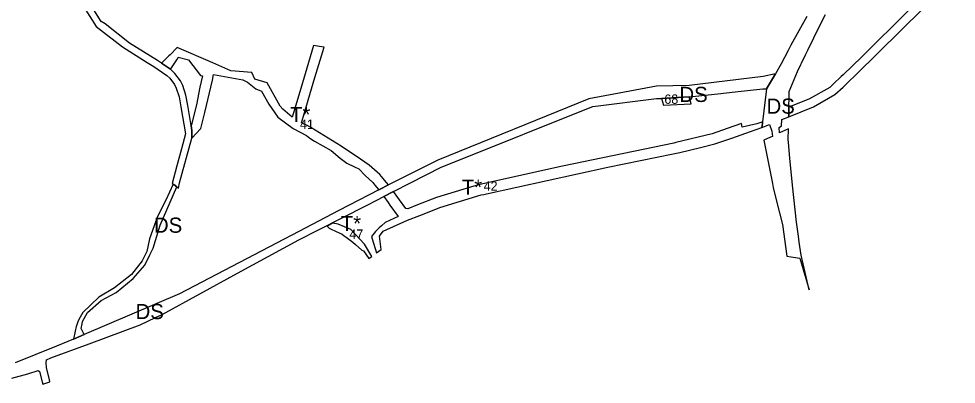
# Model space of a CAD drawing. Extents: x -535435 to -532834, y -1165802 to -1163866.
# Drawn here: x -534910 to -534109, y -1165571 to -1165258 of the extents above; entities that cross this region are included whole.
import ezdxf

# ---------------------------------------------------------------- set-up
doc = ezdxf.new("R2010")
doc.units = 0
for name, color, linetype in [('Level 23', 7, 'Continuous'), ('Level 4', 7, 'Continuous'), ('Level 44', 7, 'Continuous'), ('Level 5', 7, 'Continuous'), ('Level 61', 7, 'Continuous')]:
    doc.layers.add(name, color=color, linetype=linetype)

msp = doc.modelspace()

# ---------------------------------------------------------------- linework, layer by layer
at = {"layer": 'Level 23'}
msp.add_lwpolyline([(-534101.59, -1165203.84), (-534114.18, -1165216.32), (-534139.47, -1165241.41), (-534149.08, -1165250.94), (-534189.23, -1165290.59), (-534205.1, -1165305.99), (-534206.83, -1165307.61), (-534213.44, -1165313.82), (-534213.98, -1165314.34), (-534216.74, -1165316.93), (-534233.95, -1165326.61), (-534251.58, -1165333.78), (-534251.69, -1165338.72), (-534251.77, -1165341.96), (-534230.69, -1165333.38), (-534212.27, -1165323.02), (-534205.31, -1165316.61), (-534200.89, -1165312.54), (-534194.29, -1165306.12), (-534136.8, -1165249.37), (-534066.72, -1165179.82)], dxfattribs=at)
for points in [[(-534619.01, -1165386.65), (-534613.51, -1165392.33), (-534607, -1165398.33), (-534605.19, -1165400.54), (-534601.98, -1165404.46), (-534601.41, -1165404.16), (-534593.74, -1165400.31), (-534597.03, -1165396.3), (-534598.22, -1165394.85), (-534601.04, -1165391.41), (-534610.25, -1165383.45), (-534617.67, -1165378.23), (-534633.99, -1165367.14), (-534659.9, -1165351.07), (-534662.08, -1165350.11), (-534668.1, -1165347.2), (-534666.39, -1165341.5), (-534660.84, -1165323.06), (-534656.47, -1165308.49), (-534648.66, -1165282.51), (-534652.53, -1165281.94), (-534657.63, -1165281.08), (-534664.91, -1165305.3), (-534669.52, -1165320.65), (-534674.9, -1165338.55), (-534676.02, -1165342.29), (-534683.83, -1165335.46), (-534686.22, -1165332.95), (-534697.27, -1165312.9), (-534707.83, -1165309.96), (-534710.5, -1165304.17), (-534728.29, -1165302.64), (-534743.59, -1165295.91), (-534774.18, -1165282.74), (-534780.22, -1165288.91), (-534781.18, -1165289.9), (-534787.43, -1165296.27), (-534779.82, -1165301.36), (-534779.49, -1165300.88), (-534774.33, -1165293.32), (-534773.48, -1165292.09), (-534773.21, -1165290.92), (-534764.53, -1165293.41), (-534754.18, -1165306.73), (-534752.46, -1165306.87), (-534754.69, -1165316.58), (-534757.69, -1165331.84), (-534762.29, -1165349.74), (-534761.63, -1165353.69), (-534761.79, -1165360.41), (-534753.85, -1165351.98), (-534750.68, -1165338.49), (-534744.13, -1165310.57), (-534743.05, -1165305.98), (-534718.12, -1165310.44), (-534714.04, -1165312.46), (-534706.87, -1165318.09), (-534702.17, -1165320.06), (-534695.88, -1165331.28), (-534688.17, -1165342.38), (-534675.04, -1165351.98), (-534663.67, -1165357.97), (-534660.93, -1165360.38), (-534656.81, -1165362.85), (-534642.55, -1165370.75), (-534634.89, -1165377.36), (-534629.25, -1165381.75), (-534622.61, -1165384.94)], [(-534567.01, -1165426.39), (-534554.75, -1165421.51), (-534549.73, -1165419.5), (-534514.4, -1165408.9), (-534512.18, -1165408.41), (-534509.97, -1165407.93), (-534406.37, -1165385.09), (-534350.42, -1165373.76), (-534347.57, -1165373.21), (-534344.67, -1165372.49), (-534327.1, -1165368.26), (-534314.72, -1165365.27), (-534300.23, -1165360.21), (-534284.53, -1165354.73), (-534274.64, -1165351.27), (-534274.2, -1165347.69), (-534274.04, -1165346.4), (-534275.59, -1165346.89), (-534279.12, -1165348.18), (-534291.43, -1165350.78), (-534292.02, -1165347.81), (-534304.23, -1165352.07), (-534317.27, -1165356.63), (-534348.18, -1165364.09), (-534349.96, -1165364.5), (-534444.99, -1165384.39), (-534513.15, -1165399.41), (-534517.58, -1165400.46), (-534520.7, -1165401.39), (-534552.7, -1165411), (-534568.84, -1165417.43), (-534577.13, -1165420.74), (-534578.84, -1165420.53), (-534584.33, -1165412.96), (-534585.71, -1165411.05), (-534589.33, -1165406.05), (-534597.58, -1165410.25), (-534593.89, -1165415.47), (-534592.44, -1165417.51), (-534585.47, -1165427.37), (-534596.58, -1165432.42), (-534599.52, -1165435.21), (-534601.57, -1165437.17), (-534604.65, -1165440.1), (-534608.12, -1165444.51), (-534607.55, -1165446.4), (-534603.88, -1165458.54), (-534599.87, -1165455.71), (-534601.36, -1165444.1), (-534598.29, -1165439.76), (-534577.5, -1165430.58)], [(-534636.67, -1165433.92), (-534641.32, -1165433.01), (-534646.15, -1165435.68), (-534644.3, -1165437.19), (-534642.65, -1165438.14), (-534635.1, -1165441.55), (-534633.13, -1165442.51), (-534631.5, -1165443.83), (-534629.91, -1165445), (-534624.12, -1165449.21), (-534621.78, -1165451.3), (-534616.51, -1165456.28), (-534614.92, -1165456.72), (-534610.46, -1165463.27), (-534607.91, -1165461.42), (-534614.06, -1165451.06), (-534625.81, -1165438.39)]]:
    msp.add_lwpolyline(points, close=True, dxfattribs=at)
at = {"layer": 'Level 4'}
for points in [[(-534236.16, -1165256.09), (-534249.84, -1165280.89), (-534252.19, -1165285.28), (-534255.45, -1165291.38), (-534258.18, -1165296.74), (-534263.07, -1165305.2), (-534270.61, -1165318.24), (-534274.04, -1165346.4), (-534274.2, -1165347.69), (-534274.64, -1165351.27), (-534268.13, -1165348.62), (-534266.24, -1165354.33), (-534265.74, -1165358.75), (-534267.32, -1165359.47), (-534272.9, -1165362.02), (-534265.72, -1165399.2), (-534264.94, -1165402.42), (-534262.04, -1165414.36), (-534257.19, -1165434.29), (-534253.34, -1165461.15), (-534249.66, -1165461.74), (-534244.14, -1165462.64), (-534242.12, -1165462.96), (-534234.3, -1165490.14), (-534241.22, -1165460.36), (-534242.7, -1165449.22), (-534243.4, -1165444.03), (-534244.98, -1165432.27), (-534247.31, -1165411.07), (-534248.48, -1165400.41), (-534250.69, -1165377.47), (-534251.99, -1165363.99), (-534252.23, -1165361.54), (-534252.01, -1165352.47), (-534259.48, -1165355.88), (-534259.96, -1165351.32), (-534257.97, -1165349.66), (-534257.49, -1165344.29), (-534251.77, -1165341.96), (-534251.69, -1165338.72), (-534251.27, -1165320.44), (-534244.31, -1165303.28), (-534241.33, -1165297.17), (-534240.88, -1165296.25), (-534237.36, -1165289.01), (-534235.49, -1165285.14), (-534225.18, -1165263.79), (-534220.39, -1165254.46)], [(-534915.56, -1165565.61), (-534901.88, -1165561.94), (-534893.04, -1165558.98), (-534891.75, -1165560.02), (-534889.42, -1165568.74), (-534888.88, -1165570.88), (-534882.85, -1165568.74), (-534883.19, -1165566.76), (-534885.55, -1165558), (-534885.69, -1165556.54), (-534886.11, -1165552.64), (-534885.76, -1165550.05), (-534882.03, -1165548.34), (-534849.32, -1165536.17), (-534805.71, -1165519.94), (-534792.57, -1165513.75), (-534787.1, -1165511.18), (-534722.56, -1165475.88), (-534670.22, -1165447.23), (-534653.44, -1165438.69), (-534612.41, -1165417.8), (-534603.53, -1165413.28), (-534597.58, -1165410.25), (-534589.33, -1165406.05), (-534574.83, -1165398.66), (-534548.51, -1165385.26), (-534502.24, -1165366.65), (-534454, -1165347.26), (-534419.17, -1165333.25), (-534364.65, -1165326.48), (-534360.45, -1165326.25), (-534336.67, -1165324.94), (-534312.18, -1165322.29), (-534297.49, -1165320.71), (-534273.89, -1165318.16), (-534270.61, -1165318.24), (-534263.07, -1165305.2), (-534273.43, -1165307.68), (-534336.76, -1165315.12), (-534364.57, -1165315.97), (-534387.51, -1165320.16), (-534422.4, -1165326.53), (-534551.38, -1165379.05), (-534593.74, -1165400.31), (-534601.41, -1165404.16), (-534601.98, -1165404.46), (-534635.94, -1165422.22), (-534670.3, -1165440.18), (-534772.12, -1165493.42), (-534853.75, -1165528.43), (-534862.8, -1165532.4), (-534877.24, -1165538.36), (-534912.68, -1165552.42)], [(-534860.51, -1165521.43), (-534861.32, -1165525.37), (-534862.8, -1165532.4), (-534853.75, -1165528.43), (-534856.09, -1165523.12), (-534855.37, -1165519.3), (-534854.95, -1165517.06), (-534850.87, -1165509.4), (-534839.06, -1165499.27), (-534826.42, -1165492.24), (-534811.76, -1165480.33), (-534801.92, -1165469.07), (-534797.58, -1165460.25), (-534794.8, -1165454.57), (-534788.69, -1165434.63), (-534774.44, -1165402.06), (-534777.14, -1165399.85), (-534777.48, -1165399.64), (-534783.92, -1165413.27), (-534791.04, -1165427.36), (-534797.86, -1165446.44), (-534800.02, -1165457.14), (-534804.19, -1165465.36), (-534813.3, -1165476.94), (-534827.72, -1165488.42), (-534841.13, -1165496.3), (-534854.91, -1165509.61), (-534858.15, -1165515.35), (-534858.97, -1165517.45), (-534860.3, -1165520.88), (-534860.51, -1165521.43)]]:
    msp.add_lwpolyline(points, dxfattribs=at)
at = {"layer": 'Level 44'}
msp.add_lwpolyline([(-534859.49, -1165238.97), (-534843.37, -1165264.7), (-534820.98, -1165282.13), (-534799.91, -1165295.46), (-534794.12, -1165299.01), (-534783.15, -1165306.66), (-534780.56, -1165308.99), (-534776.55, -1165314.45), (-534774.96, -1165317.63), (-534772.56, -1165324.91), (-534771.12, -1165333.46), (-534767.05, -1165356.72), (-534770.47, -1165369.48), (-534774.35, -1165383.99), (-534778.38, -1165399.06), (-534777.48, -1165399.64), (-534777.14, -1165399.85), (-534774.44, -1165402.06), (-534773.1, -1165402.96), (-534772.1, -1165398.4), (-534761.79, -1165360.41), (-534761.63, -1165353.69), (-534762.29, -1165349.74), (-534762.61, -1165347.87), (-534765.2, -1165332.46), (-534766.72, -1165323.47), (-534769.4, -1165315.33), (-534771.41, -1165311.31), (-534776.08, -1165304.95), (-534779.82, -1165301.36), (-534790.88, -1165293.95), (-534814.86, -1165279.07), (-534835.81, -1165262.59), (-534839.01, -1165260.41), (-534845.4, -1165250.42)], dxfattribs=at)
at = {"layer": 'Level 5'}
msp.add_lwpolyline([(-534335.05, -1165330.86), (-534336.67, -1165324.94), (-534360.45, -1165326.25), (-534358.83, -1165332.17), (-534335.05, -1165330.86)], dxfattribs=at)

# ---------------------------------------------------------------- texts
at = {"layer": 'Level 23'}
for p in [(-534677.75, -1165346.62), (-534531.05, -1165408.72), (-534634.44, -1165439.85)]:
    msp.add_text('T*', height=13, dxfattribs=at).set_placement(p)
at = {"layer": 'Level 4'}
for p in [(-534270.69, -1165339.4), (-534794.03, -1165441.26), (-534809.72, -1165515.14)]:
    msp.add_text('DS', height=13, dxfattribs=at).set_placement(p)
at = {"layer": 'Level 5'}
msp.add_text('DS', height=13, dxfattribs=at).set_placement((-534345.11, -1165329.37))
at = {"layer": 'Level 61'}
for s, p in [('68', (-534358, -1165330.93)), ('41', (-534669.28, -1165352.4)), ('42', (-534512.4, -1165405.35)), ('47', (-534627.11, -1165446.45))]:
    msp.add_text(s, height=8, dxfattribs=at).set_placement(p)

doc.saveas('drawing.dxf')
